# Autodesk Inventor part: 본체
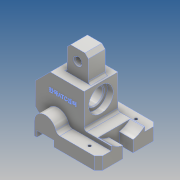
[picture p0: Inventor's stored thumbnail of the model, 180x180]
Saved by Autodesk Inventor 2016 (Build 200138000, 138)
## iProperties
Created: 2016-11
Part Number: 본체
Material: 알루미늄 6061
Document SubType Name: Modeling
Designer: Administrator
Density: 2.7 g/cm^3
Appearance: 알루미늄 - 평지
Mass: 470.029 g
Surface Area: 319.728 cm^2
Volume: 174.085 cm^3
Author: Administrator
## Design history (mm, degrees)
sketch "스케치1"
  geometry: L1 (-31.5, -7.5)-(21.5, -7.5); L2 (18.5, 7.5)-(-31.5, 7.5); L3 (-31.5, 7.5)-(-31.5, -7.5); L4 (44.5, 7.5)-(44.5, -7.5); L5 (44.5, -7.5)-(41.5, -7.5); L6 (41.5, -7.5)-(41.5, -0.5); L7 (41.5, -0.5)-(21.5, -0.5); L8 (21.5, -0.5)-(21.5, -7.5); A1 r 13 centre (31.5, 7.5) between (44.5, 7.5) and (18.5, 7.5); 2 further points
  constraints: 16 end point, 3 horizontal alignment, 3 perpendicular, 2 parallel, 2 point on circle, 2 vertical, 1 centre point, 1 horizontal, 1 midpoint, 1 tangent
  dimensions: "d1" = 15 distance of L2.end L1.start; "d2" = 26 diameter of A1; "d3" = 3 distance of L4.end L5.end; "d8" = 44.5 distance from line of point (0, 0) L4; "d9" = 63 distance from line of L3 A1.centre; "d28" = 7 distance of L5.end L6.end; "d29" = 20 distance of L6.end L7.end
extrude "돌출1" new body sketch "스케치1" distance "d10" = 70; taper "d11" = 0 deg
node "작업 평면1"
sketch "스케치2"
  geometry: L1 (-31.5, -7.5)-(21.5, -7.5) reference; L2 (41.5, -7.5)-(44.5, -7.5) reference; L3 (44.5, -7.5)-(44.5, 7.5) reference; L4 (18.5, 7.5)-(-31.5, 7.5) reference; L5 (-31.5, 7.5)-(-31.5, -7.5) reference; L6 (58.5, 4.5)-(58.5, 34.5); L7 (58.5, 34.5)-(40.5, 52.5); L8 (40.5, 52.5)-(0.5, 52.5); L9 (18.5, 7.5)-(-31.5, 7.5) reference; L10 (0.5, 52.5)-(0.5, 12.5); L11 (0.5, 12.5)-(-31.5, 12.5); L12 (-31.5, 12.5)-(-31.5, 7.5); L13 (21.5, -7.5)-(21.5, -0.5) reference; L14 (21.5, -0.5)-(41.5, -0.5) reference; L15 (41.5, -0.5)-(41.5, -7.5) reference; L16 (58.5, 4.5)-(-31.5, 4.5); L17 (-31.5, 7.5)-(-31.5, -7.5) reference; L18 (-31.5, 7.5)-(-31.5, 4.5); A1 r 13 centre (31.5, 7.5) between (44.5, 7.5) and (18.5, 7.5) reference; 1 further point
  constraints: 16 end point, 4 perpendicular, 1 collinear, 1 point on line, 1 vertical
  dimensions: "d13" = 20 distance between parallel lines of L1 L11; "d14" = 90 distance between parallel lines of L12 L6; "d15" = 18 horizontal distance of L6.end L7.end; "d16" = 45 deg angle of L8 L7; "d20" = 58 horizontal distance of L6.end L8.end; "d85" = 60 distance between parallel lines of L1 L8; "d87" = 48 vertical distance of L7.end L6.start
extrude "돌출2" join sketch "스케치2" stored distance "d21" = 40; taper "d22" = 0 deg
sketch "스케치3"
  geometry: L1 (40.5, 52.5)-(0.5, 52.5) reference; L2 (30.5, 52.5)-(30.5, 82.5); L3 (30.5, 82.5)-(5.5, 82.5); L4 (5.5, 82.5)-(5.5, 52.5); L5 (-31.5, -7.5)-(21.5, -7.5) reference; 1 further point
  constraints: 6 end point, 2 perpendicular, 2 point on line, 1 vertical
  dimensions: "d23" = 5 distance from line of L1.end L4; "d24" = 25 distance between parallel lines of L2 L4; "d25" = 90 distance between parallel lines of L5 L3
extrude "돌출3" join sketch "스케치3" stored distance "d26" = 20; taper "d27" = 0 deg
node "작업 평면2"
sketch "스케치4"
  geometry: L1 (-27.169, 34.5)-(99.342, 34.5); L2 (0, -7.5)-(70, -7.5) reference; L3 (45, 82.5)-(25, 82.5) reference; L4 (35, 82.5)-(35, -7.5); L5 (15, 12.5)-(55, 12.5) reference; L6 (29, 6.127)-(29, -7.5); L7 (41, 6.127)-(41, -7.5); L8 (16.106, 12.5)-(53.894, 12.5); L9 (29, -7.5)-(41, -7.5); A1 r 29 centre (35, 34.5) between (16.106, 12.5) and (29, 6.127); A2 r 29 centre (35, 34.5) between (41, 6.127) and (53.894, 12.5); 1 further point
  constraints: 12 end point, 6 point on line, 4 point on circle, 2 centre point, 2 horizontal, 2 midpoint, 1 collinear, 1 concentric, 1 perpendicular, 1 vertical, 1 other
  dimensions: "d31" = 42 distance between parallel lines of L2 L1; "d33" = 12 distance between parallel lines of L7 L6; "d34" = 29 radius of A1
extrude "돌출4" cut sketch "스케치4" stored distance "d35" = 20; taper "d36" = 0 deg
sketch "스케치5"
  geometry: L1 (50, 0)-(50, 15) reference; L2 (-26, 0)-(-26, 70) reference; L3 (-26, 35)-(62.627, 35); 3 further points
  constraints: 2 end point, 1 horizontal, 1 midpoint, 1 symmetric about line
  dimensions: "d37" = 18 distance from line of L1 point (32, 7.5); "d38" = 55 distance of point (32, 7.5) point (32, 62.5)
hole "구멍1" sketch "스케치5" at (32, 7.5), (32, 62.5) diameter "d39" = 3.242; stored, may be unused: countersink angle "d43" = 90 deg, drill point angle "d45" = 118 deg; dims "d40" = 8, "d41" = 4, "d42" = 2, "d44" = 11.8
sketch "스케치6"
  geometry: L1 (69.482, 34.5)-(-10.893, 34.5); L2 (44.5, 7.5)-(58.5, 4.5) reference; L3 (0.5, 52.5)-(0.5, 12.5) reference; L4 (0.5, 49)-(7.5, 49); L5 (7.5, 49)-(7.5, 44.5); L6 (7.5, 44.5)-(64.5, 44.5); L7 (64.5, 44.5)-(64.5, 34.5); L8 (64.5, 34.5)-(0.5, 34.5); L9 (0.5, 49)-(0.5, 34.5); L10 (-31.5, -7.5)-(-15, -7.5) reference; 1 further point
  constraints: 14 end point, 4 perpendicular, 4 point on line, 2 horizontal
  dimensions: "d47" = 29 diameter of L4 L1; "d48" = 20 diameter of L6 L1; "d49" = 7 distance between parallel lines of L3 L5; "d53" = 64 distance between parallel lines of L3 L7; "d86" = 42 distance between parallel lines of L10 L1
revolve "회전1" sketch "스케치6" stored, may be unused: angle "d54" = 90 deg
sketch "스케치9"
  geometry: L1 (-5.5, 82.5)-(-30.5, 82.5) reference; L2 (31.5, -7.5)-(-21.5, -7.5) reference; C1 r 4 at (-18, 69.5); 2 further points
  constraints: 1 centre point, 1 midpoint, 1 vertical alignment
  dimensions: "d88" = 8 diameter of C1; "d89" = 77 distance from line of L2 C1.centre
extrude "돌출7" cut sketch "스케치9" stored distance "d90" = 0.5; taper "d91" = 0 deg
chamfer "모따기7" distance "d92" = 1; stored, may be unused: second distance "d93" = 2, angle "d94" = 45 deg
chamfer "모따기8" distance "d95" = 1; stored, may be unused: second distance "d96" = 2, angle "d97" = 45 deg
fillet "모깎기4" dims "d98" = 3
fillet "모깎기5" dims "d99" = 5
chamfer "모따기9" distance "d100" = 5; stored, may be unused: second distance "d101" = 2, angle "d102" = 45 deg
chamfer "모따기10" distance "d103" = 4; stored, may be unused: second distance "d104" = 2, angle "d105" = 45 deg
sketch "스케치10"
  geometry: L1 (-0.5, 12.5)-(-0.5, 52.5) reference; L2 (-0.5, 52.5)-(-40.5, 52.5) reference; 2 further points
  constraints: 1 other
  dimensions: "d106" = 18 distance from line of L2 point (-25.5, 34.5); "d107" = 25 distance from line of L1 point (-25.5, 34.5)
extrude "돌출8" join sketch "스케치10" distance "d108" = 0.5; taper "d109" = 0 deg
chamfer "모따기11" distance "d110" = 1; stored, may be unused: second distance "d111" = 2, angle "d112" = 45 deg
chamfer "모따기12" distance "d113" = 4; stored, may be unused: second distance "d114" = 2, angle "d115" = 45 deg
fillet "모깎기6" dims "d116" = 3
fillet "모깎기1" dims "d60" = 5
chamfer "모따기1" distance "d61" = 4; stored, may be unused: second distance "d62" = 2, angle "d63" = 45 deg
chamfer "모따기2" distance "d64" = 4; stored, may be unused: second distance "d65" = 2, angle "d66" = 45 deg
chamfer "모따기3" distance "d67" = 5; stored, may be unused: second distance "d68" = 2, angle "d69" = 45 deg
chamfer "모따기4" distance "d70" = 1; stored, may be unused: second distance "d71" = 2, angle "d72" = 45 deg
fillet "모깎기2" dims "d73" = 3
fillet "모깎기3" dims "d80" = 3
sketch "스케치8"
  geometry: L1 (-0.5, 15.5)-(-0.5, 52.5) reference; L2 (-0.5, 52.5)-(-40.5, 52.5) reference; 2 further points
  constraints: 1 other
  dimensions: "d81" = 18 distance from line of L2 point (-25.5, 34.5); "d82" = 25 distance from line of L1 point (-25.5, 34.5)
extrude "돌출6" join sketch "스케치8" distance "d83" = 0.5; taper "d84" = 0 deg
node "솔리드1"
node "투영된 루프1"
other parameters: "d12" = 35, "d30" = 15, "d32" = 58
